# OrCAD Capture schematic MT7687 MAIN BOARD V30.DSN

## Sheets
1 4_LED: size C; title: MT76x7 Main Board; rev: 3.0; company: MediaTek Inc.; note: 4_LED
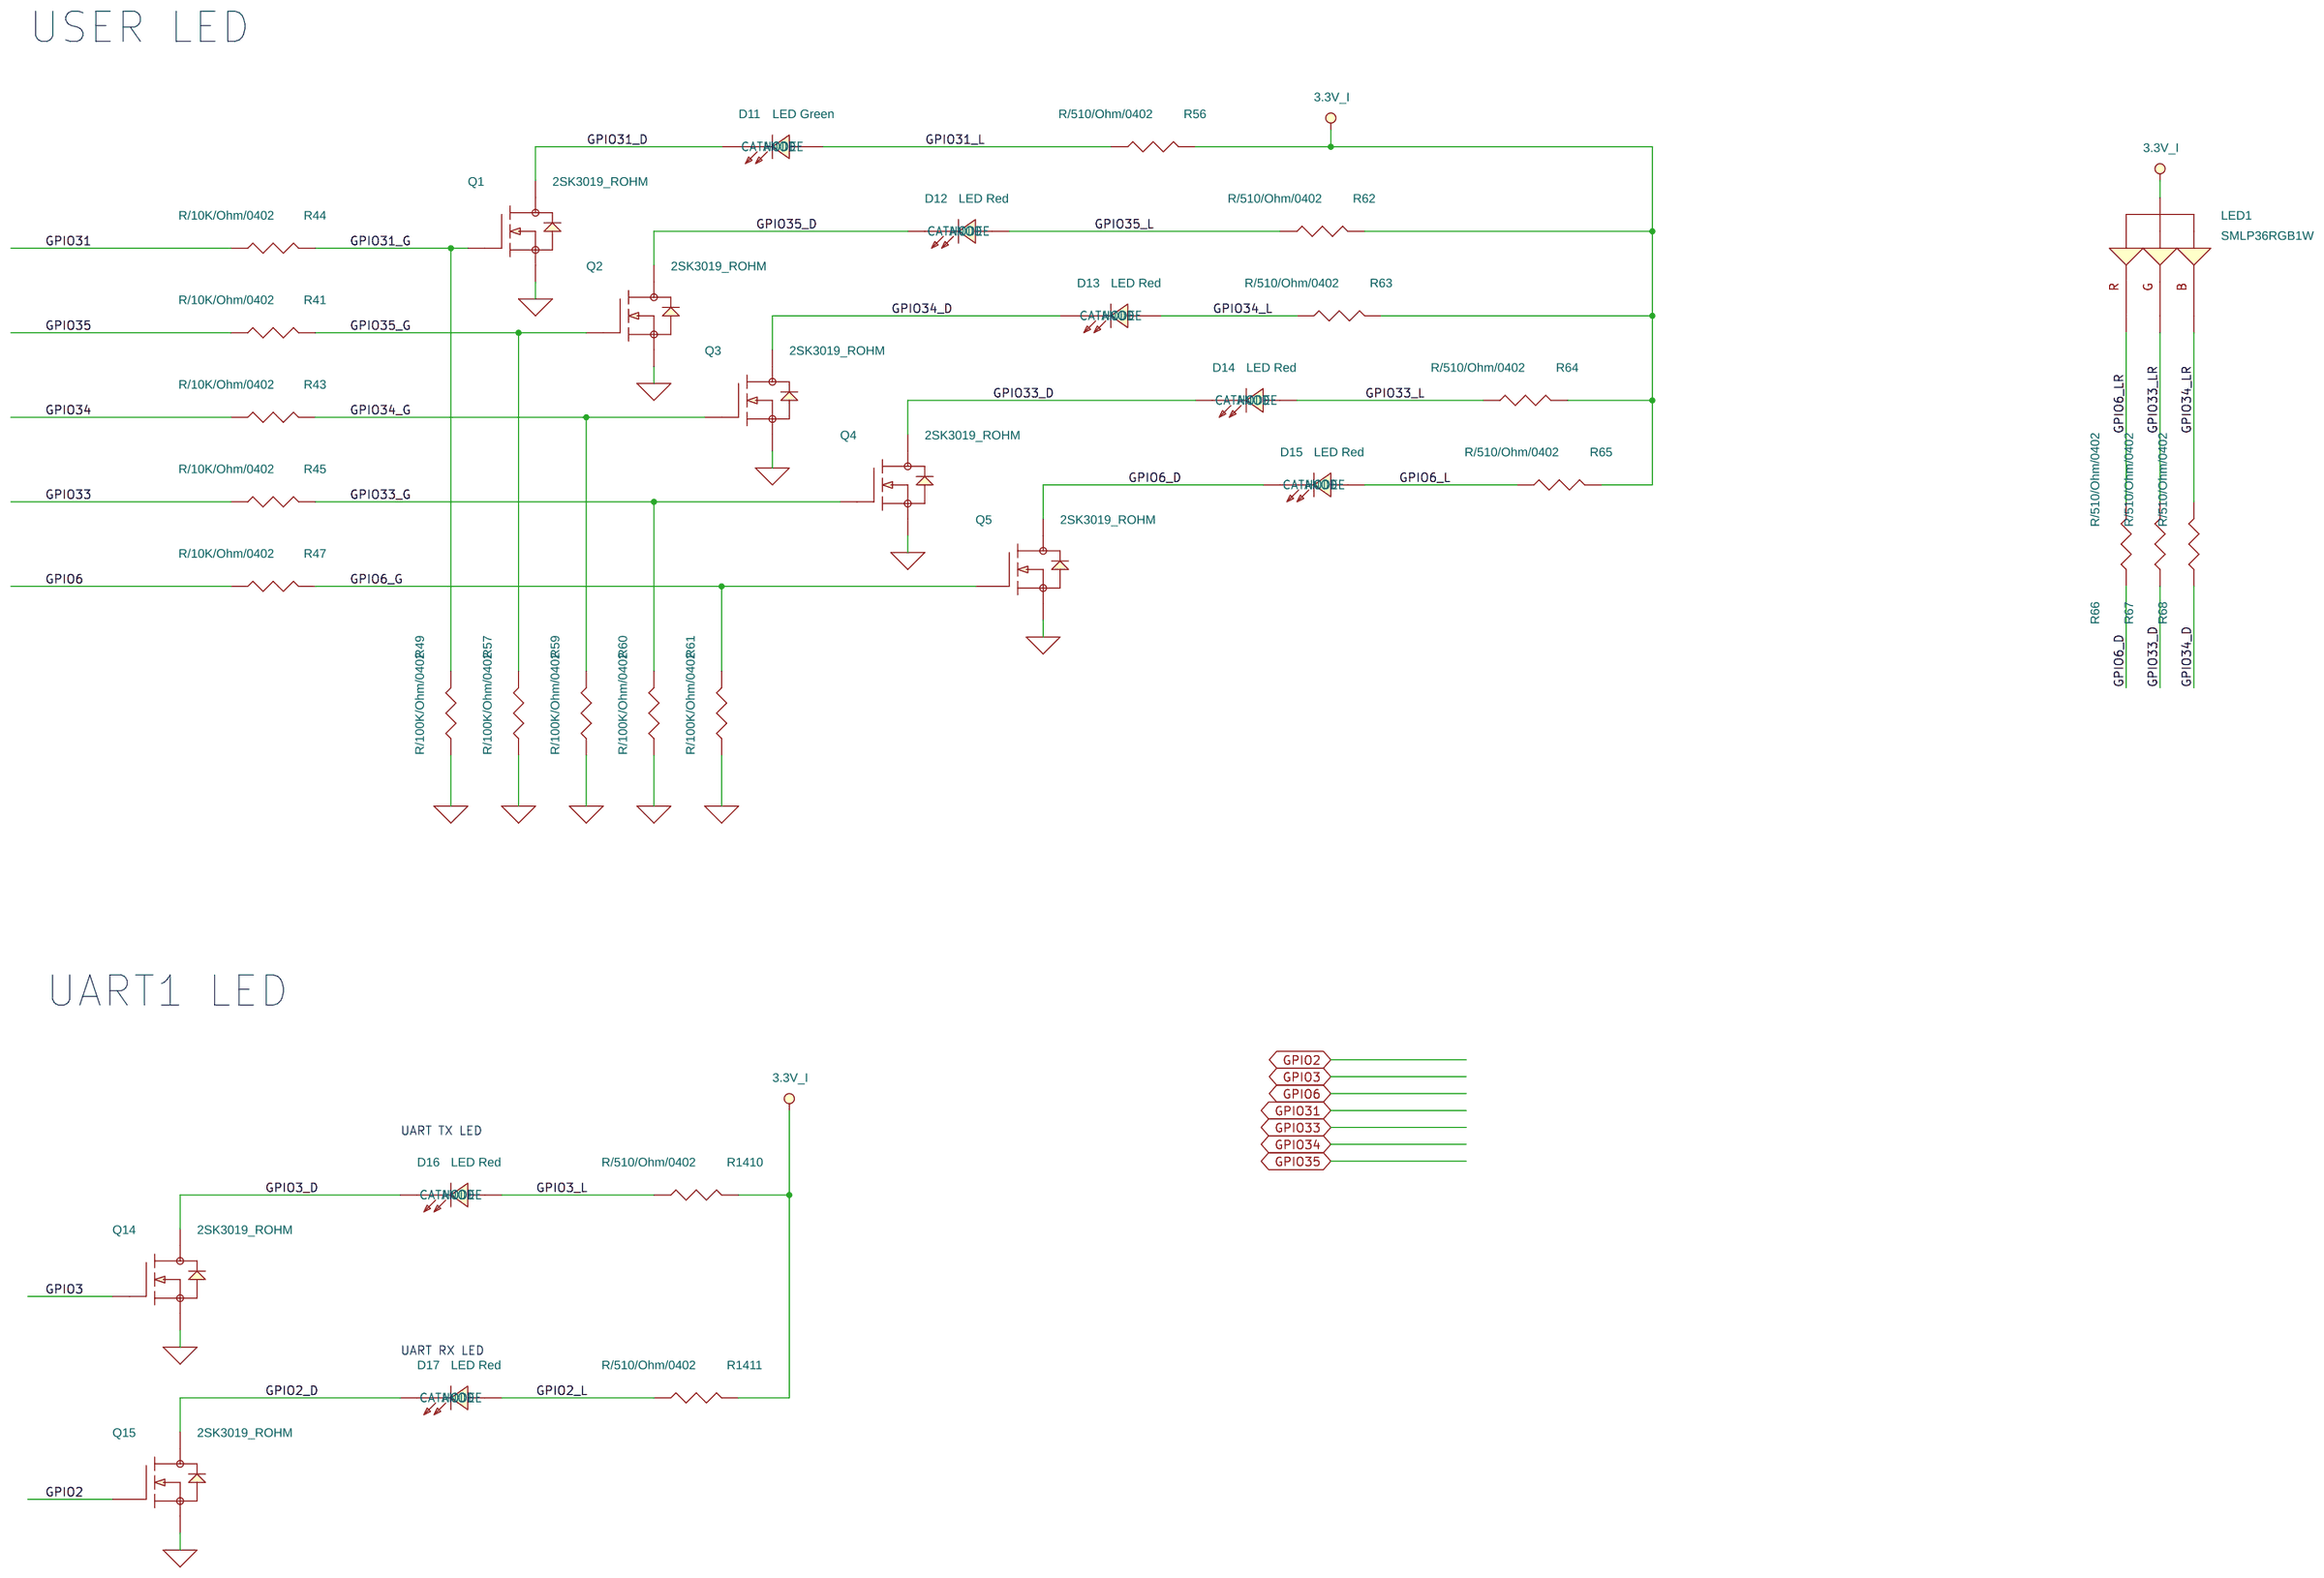
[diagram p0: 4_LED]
2 3_USB: size C; note: 3_USB
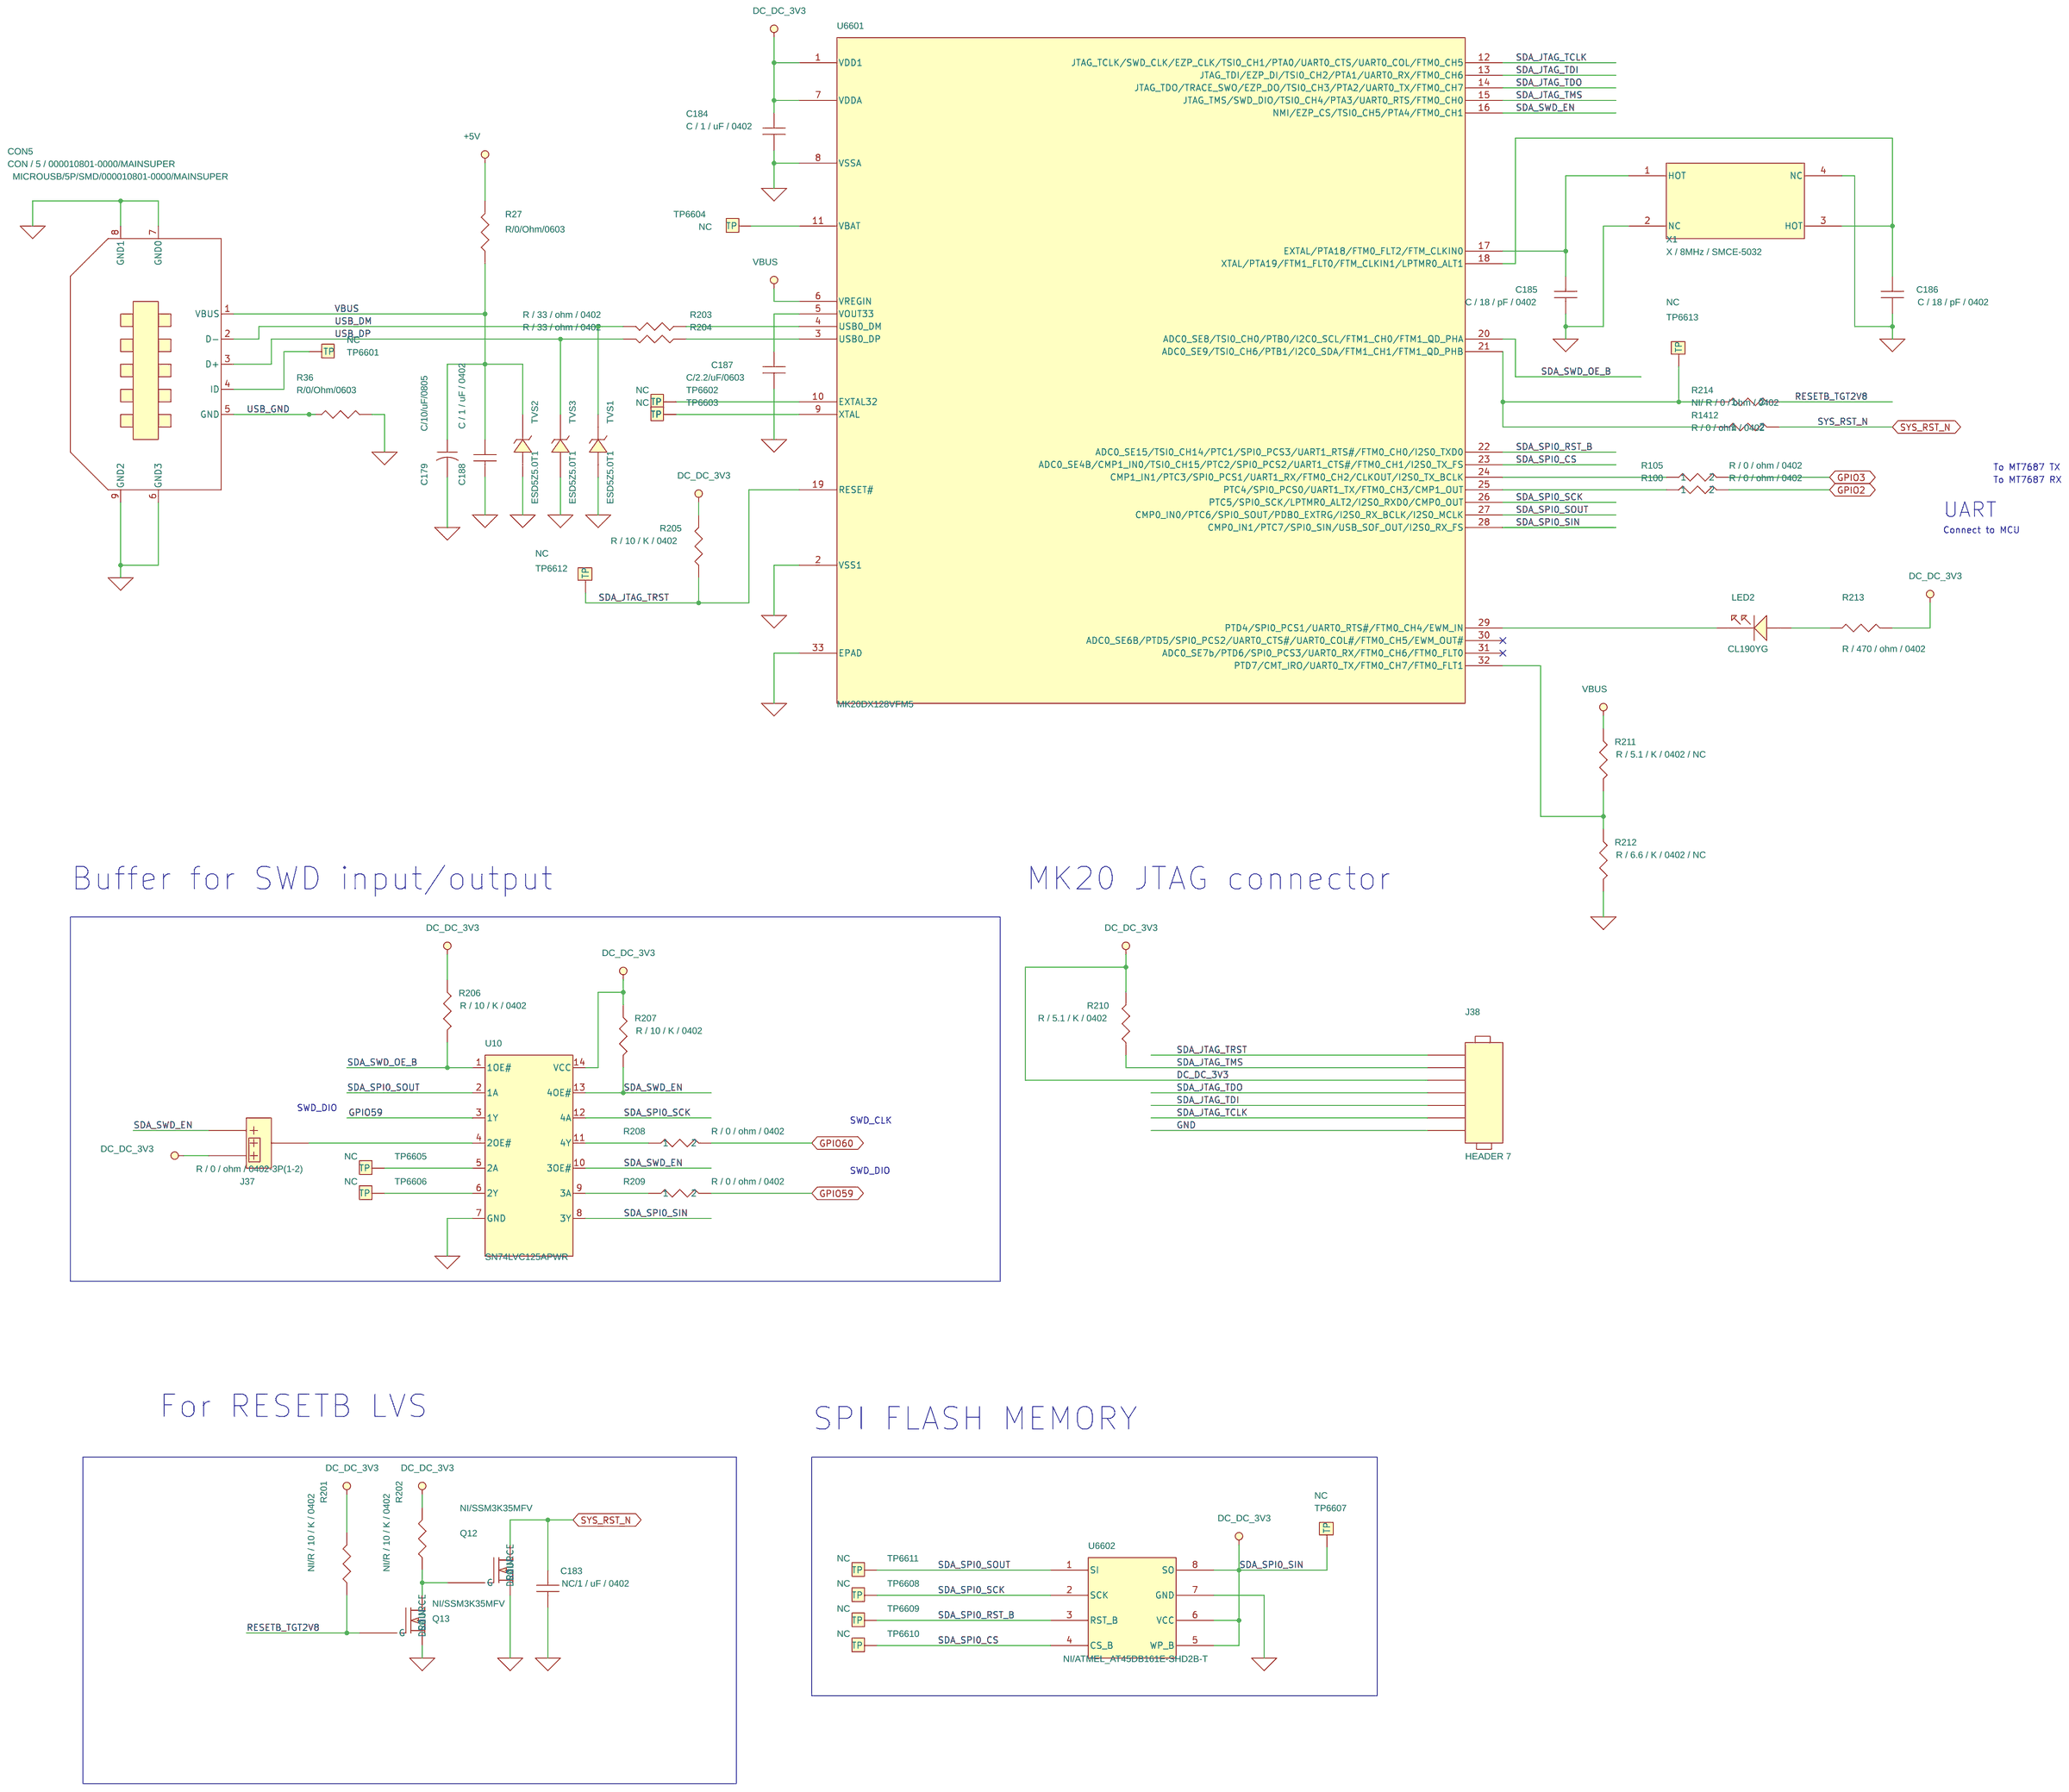
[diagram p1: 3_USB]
3 1_Power Tree: size C; note: 1-Power Tree
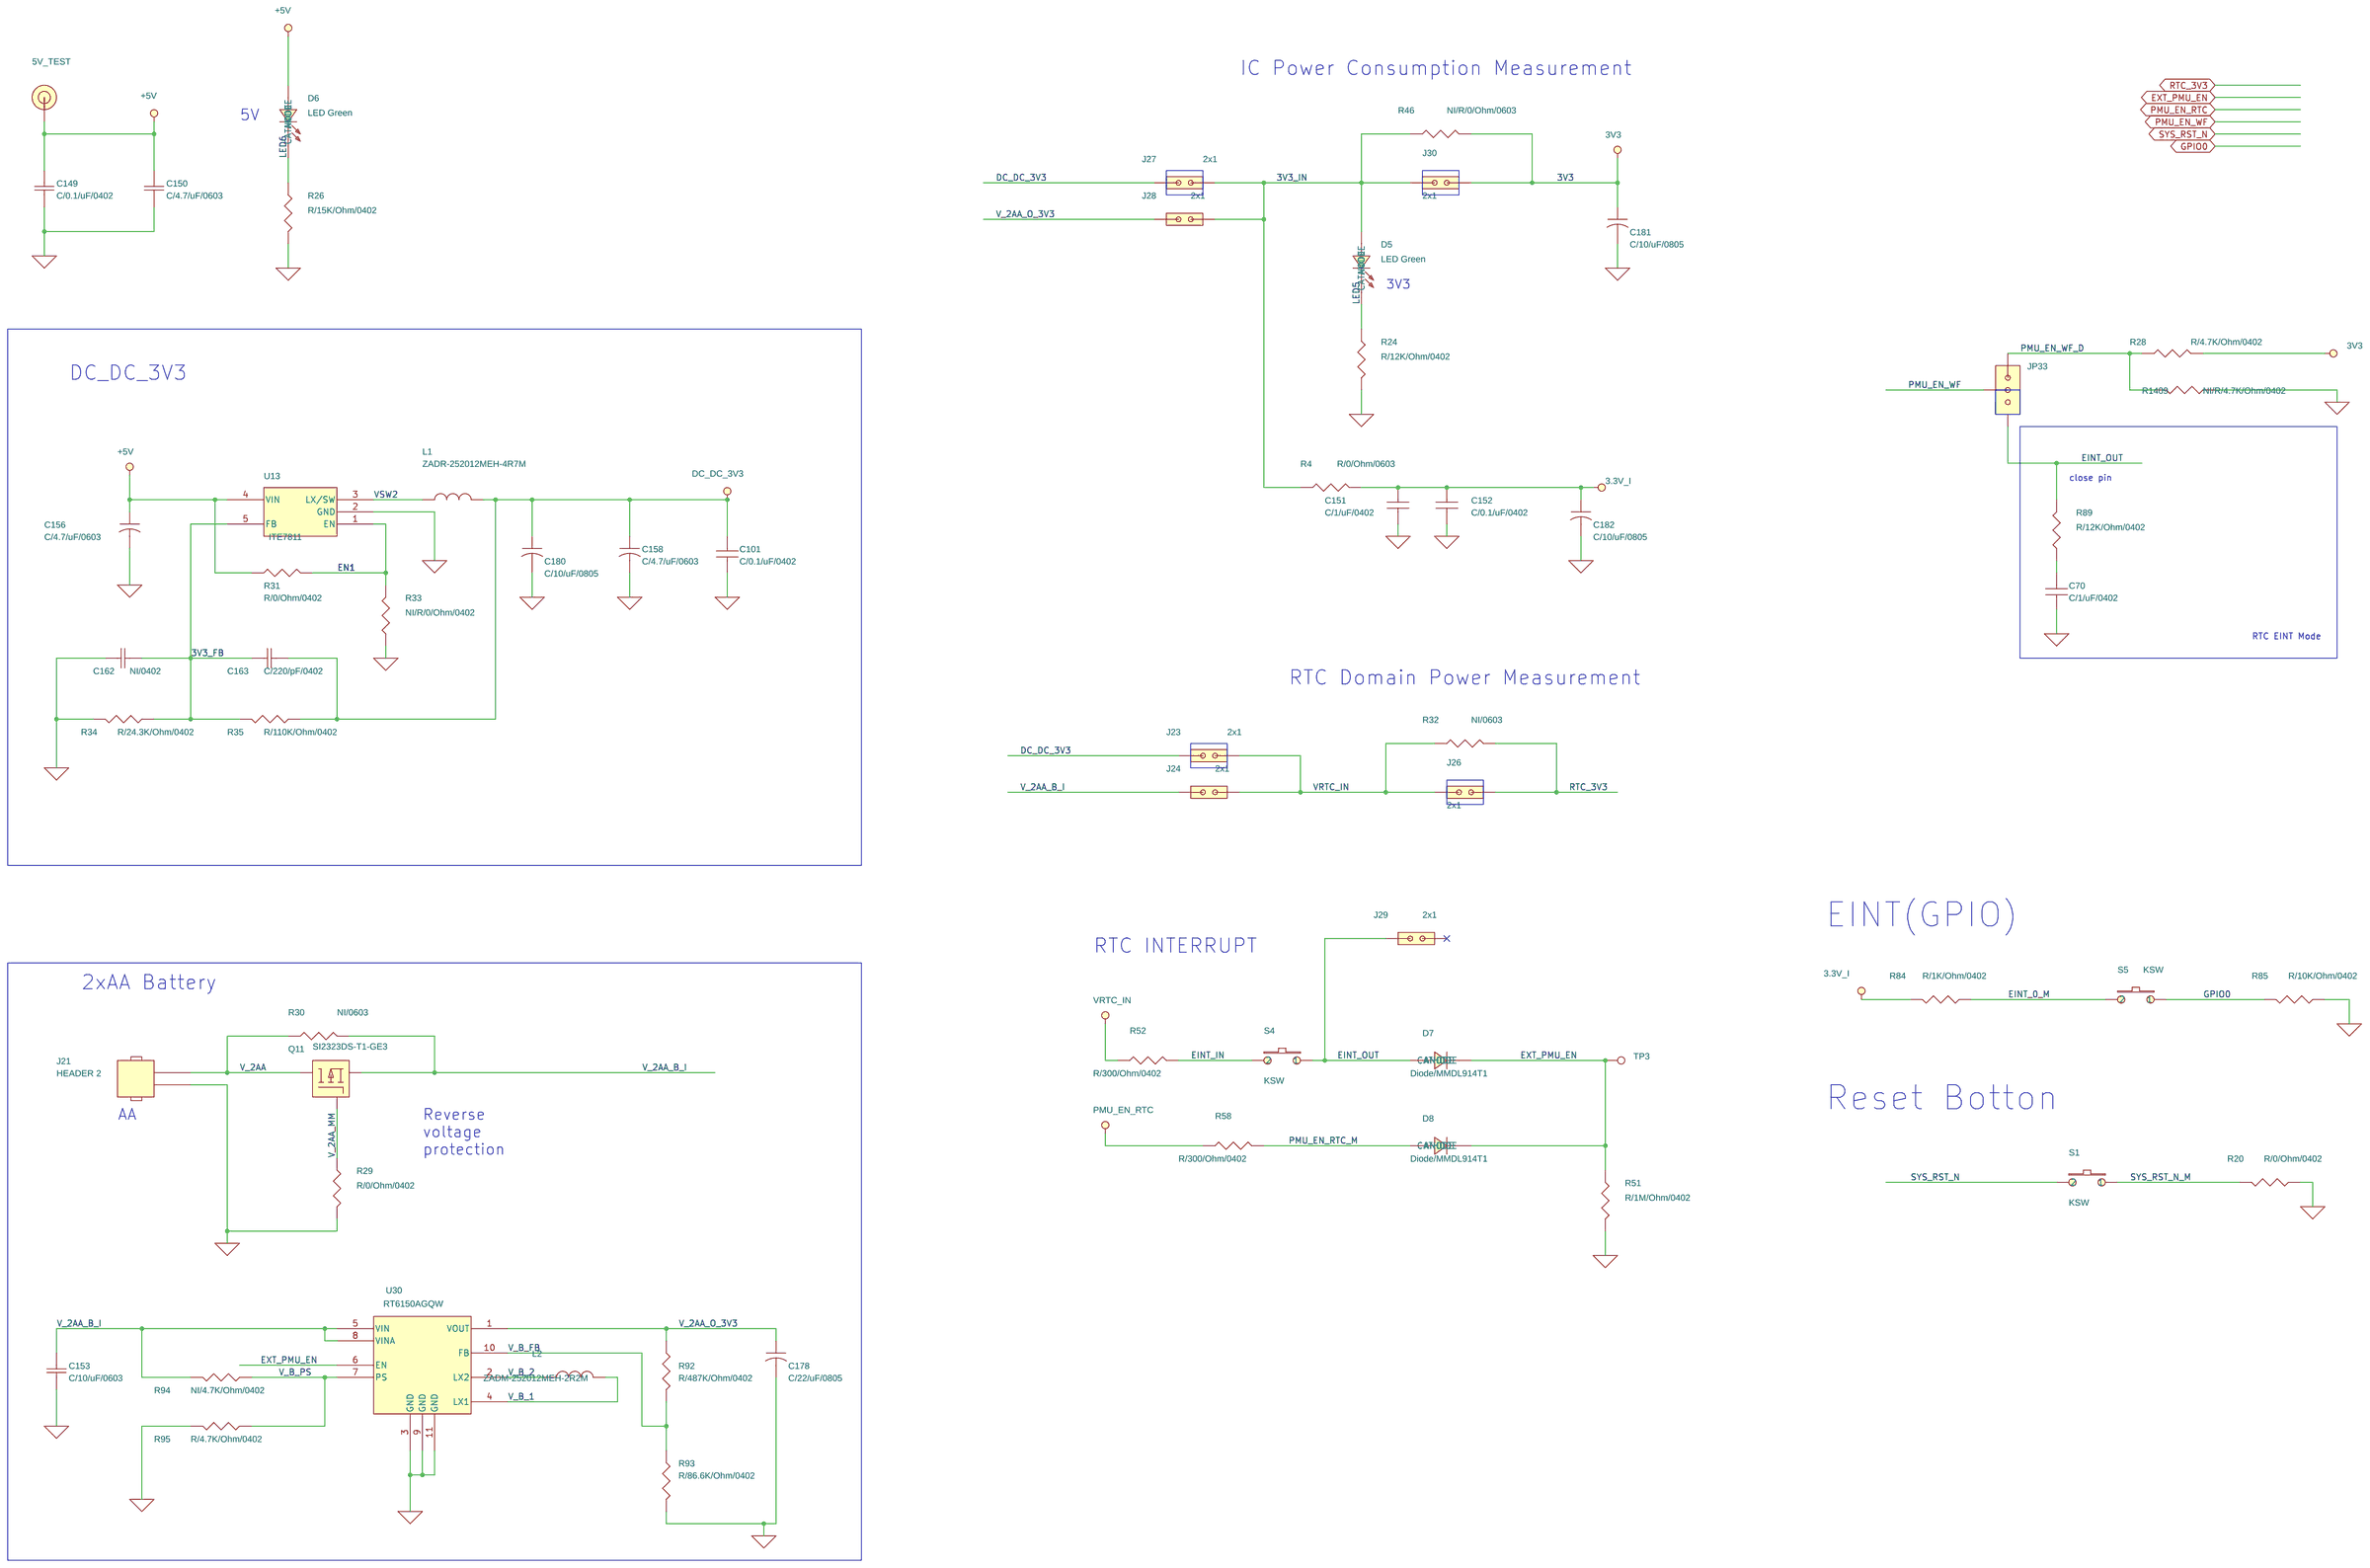
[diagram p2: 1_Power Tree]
4 2_Test Interface: size C; note: 2_Test Interface
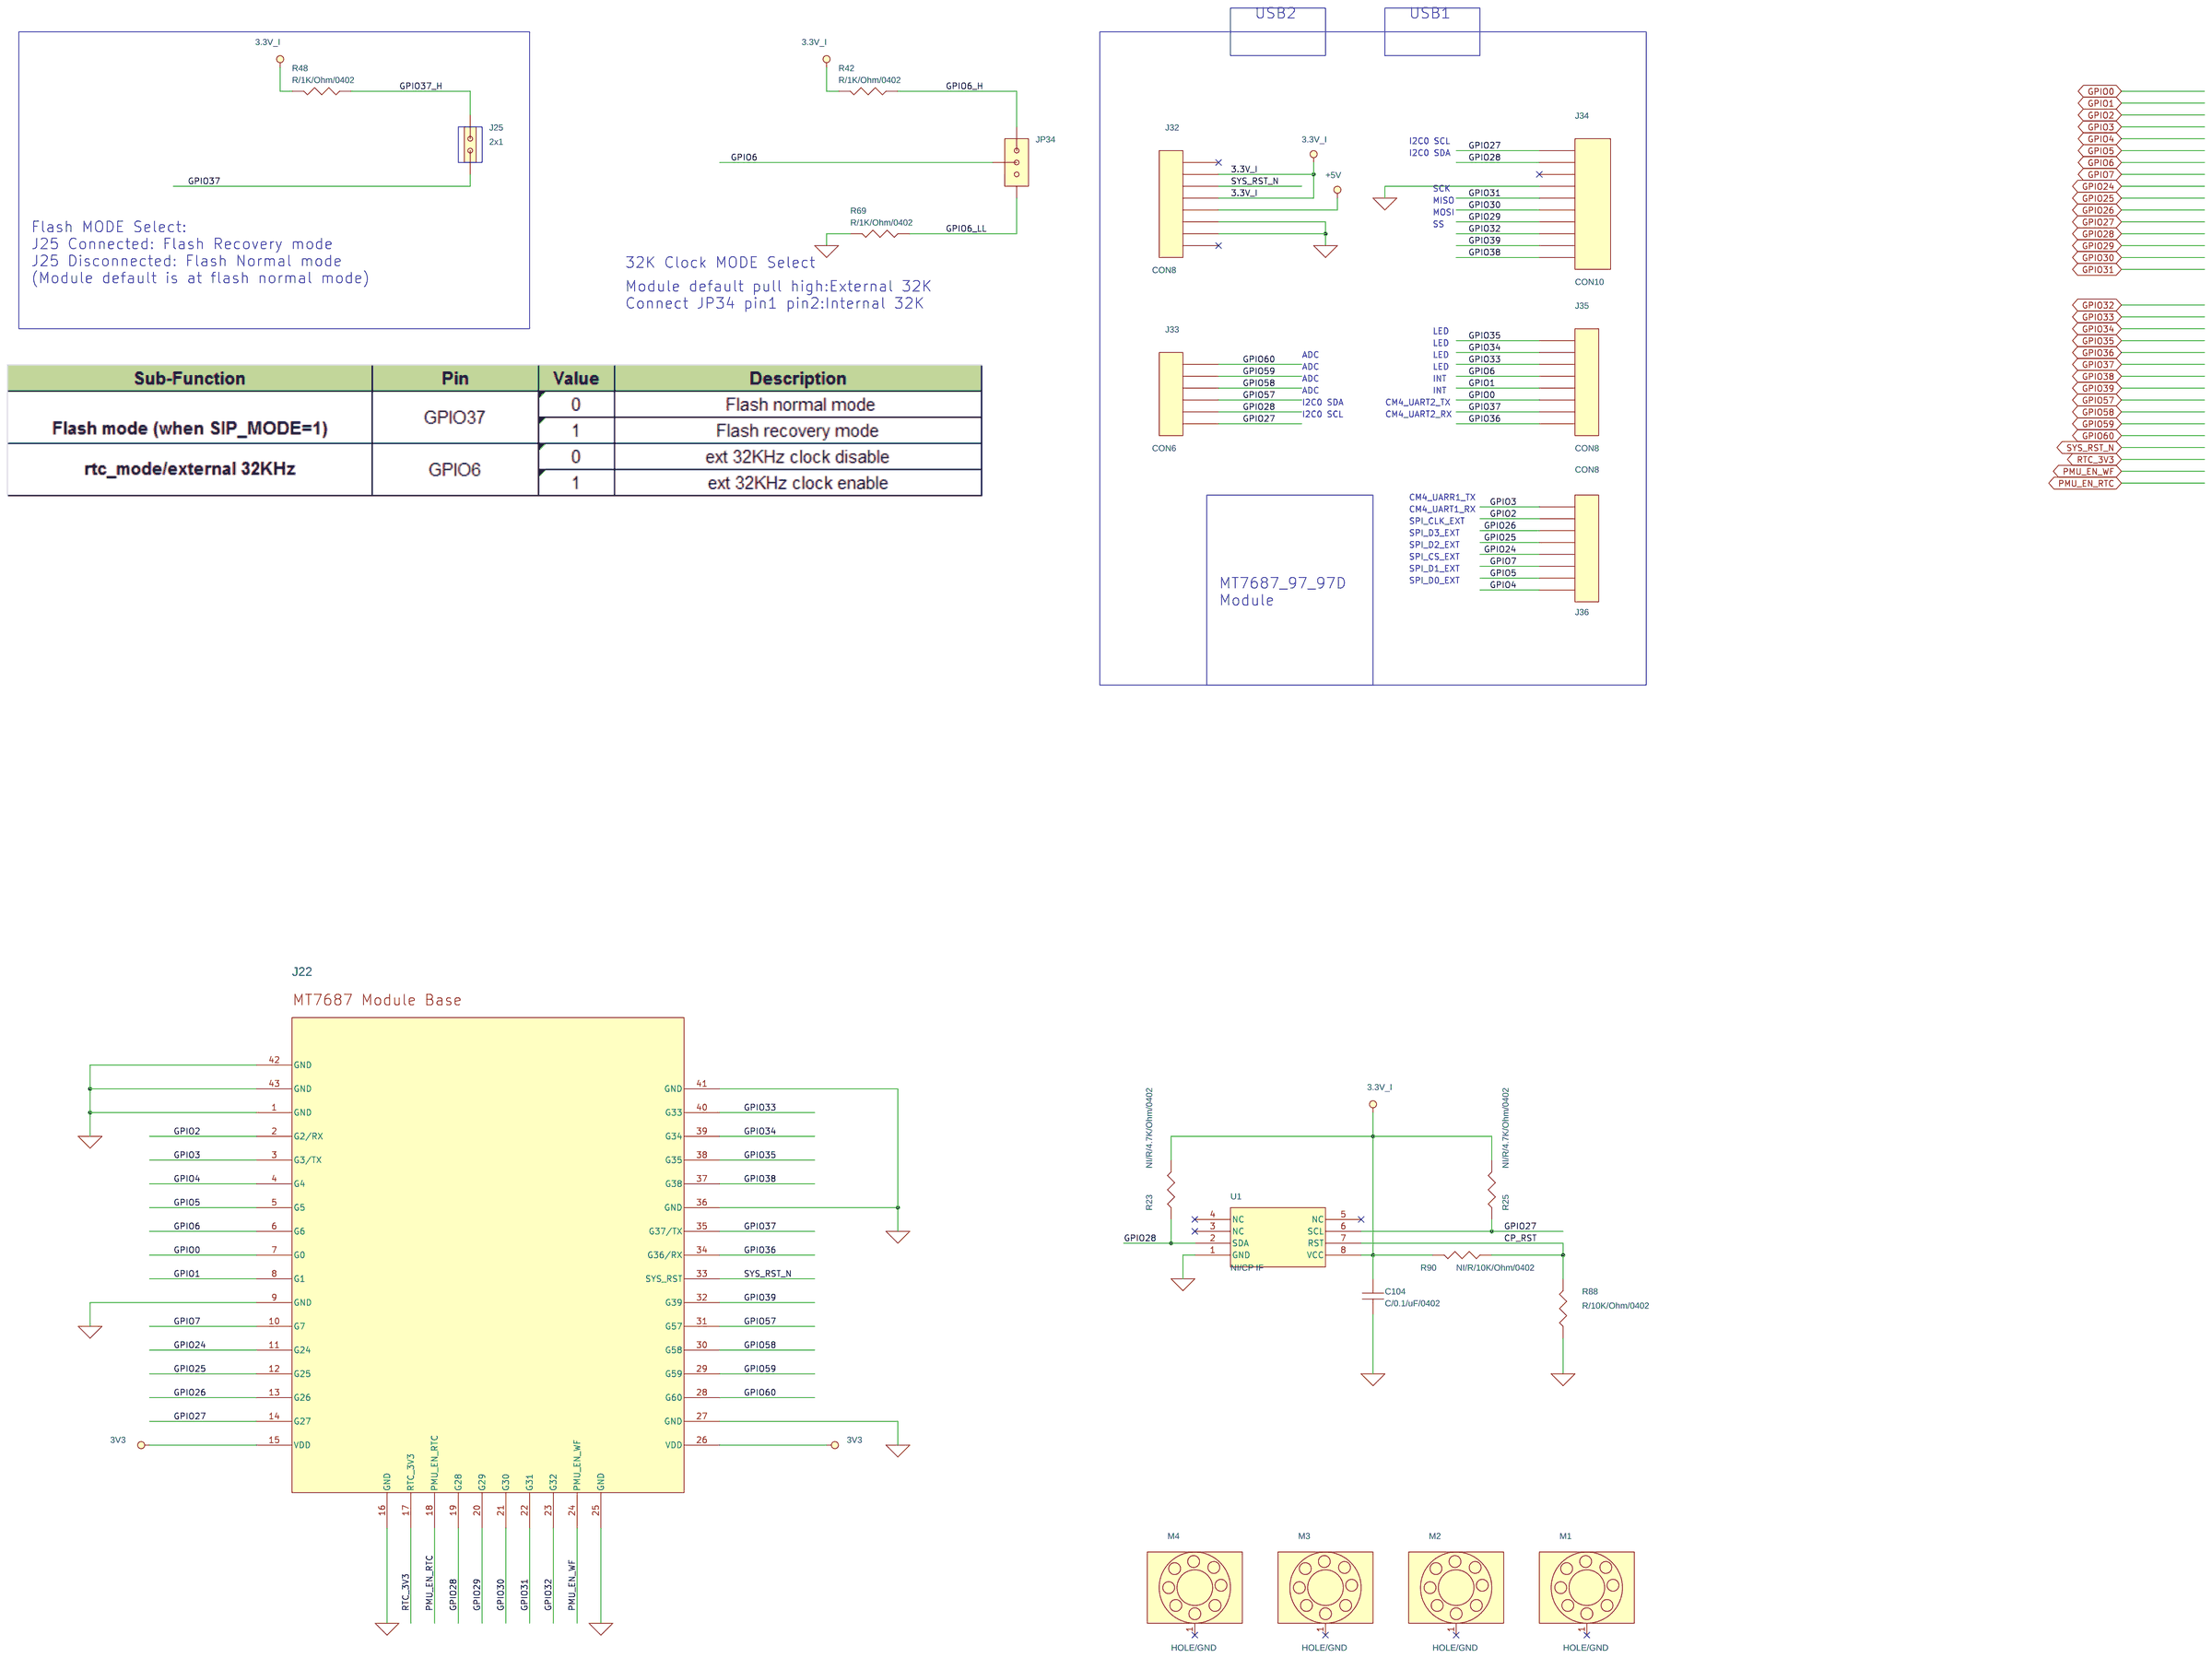
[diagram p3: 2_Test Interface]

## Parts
sheet 1_Power Tree
5V_TEST  TP-ICT  [HOLE/PTH/R1D0.6]
C70  C/1/uF/0402  [C0402]
C101  C/0.1/uF/0402  [C0402]
C149  C/0.1/uF/0402  [C0402]
C150  C/4.7/uF/0603  [C0603]
C151  C/1/uF/0402  [C0402]
C152  C/0.1/uF/0402  [C0402]
C153  C/10/uF/0603  [C0603]
C156  C/4.7/uF/0603  [C0603]
C158  C/4.7/uF/0603  [C0603]
C162  NI/0402  [C0402]
C163  C/220/pF/0402  [C0402]
C178  C/22/uF/0805  [C0805]
C180  C/10/uF/0805  [C0805]
C181  C/10/uF/0805  [C0805]
C182  C/10/uF/0805  [C0805]
D5  LED Green  [LED/SMD/0603]
D6  LED Green  [LED/SMD/0603]
D7  Diode/MMDL914T1  [SOD-323/SMD/MMDL914T1]
D8  Diode/MMDL914T1  [SOD-323/SMD/MMDL914T1]
J21  HEADER 2  [DIP2/P2.54]
J23  2x1  [JP2/DIP/P2.54]
J24  2x1  [JP2/DIP/P2.54]
J26  2x1  [JP2/DIP/P2.54]
J27  2x1  [JP2/DIP/P2.54]
J28  2x1  [JP2/DIP/P2.54]
J29  2x1  [JP2/DIP/P2.54]
J30  2x1  [JP2/DIP/P2.54]
JP33  3x1  [JP3/DIP/P2.54]
L1  ZADR-252012MEH-4R7M  [L/IND/SMD/VLS252010T]
L2  ZADM-252012MEH-2R2M  [L/IND/SMD/VLS252012E]
Q11  SI2323DS-T1-GE3  [SOT23/3P/SMD/SI2323DS]
R4  R/0/Ohm/0603  [R0603]
R20  R/0/Ohm/0402  [R0402]
R24  R/12K/Ohm/0402  [R0402]
R26  R/15K/Ohm/0402  [R0402]
R28  R/4.7K/Ohm/0402  [R0402]
R29  R/0/Ohm/0402  [R0402]
R30  NI/0603  [R0603]
R31  R/0/Ohm/0402  [R0402]
R32  NI/0603  [R0603]
R33  NI/R/0/Ohm/0402  [R0402]
R34  R/24.3K/Ohm/0402  [R0402]
R35  R/110K/Ohm/0402  [R0402]
R46  NI/R/0/Ohm/0603  [R0603]
R51  R/1M/Ohm/0402  [R0402]
R52  R/300/Ohm/0402  [R0402]
R58  R/300/Ohm/0402  [R0402]
R84  R/1K/Ohm/0402  [R0402]
R85  R/10K/Ohm/0402  [R0402]
R89  R/12K/Ohm/0402  [R0402]
R92  R/487K/Ohm/0402  [R0402]
R93  R/86.6K/Ohm/0402  [R0402]
R94  NI/4.7K/Ohm/0402  [R0402]
R95  R/4.7K/Ohm/0402  [R0402]
R1409  NI/R/4.7K/Ohm/0402  [R0402]
S1  KSW  [SW4P/DIP/WCP]
S4  KSW  [SW4P/DIP/WCP]
S5  KSW  [SW4P/DIP/WCP]
TP3  TP-SMD  [TP-SMD]
U13  ITE7811  [TSOT-25/SMD/IT7811TS]
U30  RT6150AGQW  [WDFN10/SMD/P0.5/RT6150]
sheet 2_Test Interface
C104  C/0.1/uF/0402  [C0402]
J22  MT7687 Module  [MODULE/43P/SMD/SB-MT7687-1]
J25  2x1  [JP2/DIP/P2.54]
J32  CON8  [DIP8/P2.54]
J33  CON6  [DIP6/P2.54]
J34  CON10  [DIP10/P2.54]
J35  CON8  [DIP8/P2.54]
J36  CON8  [DIP8/P2.54]
JP34  3x1  [JP3/DIP/P2.54]
M1  HOLE/GND  [HOLE/NPTH/D3]
M2  HOLE/GND  [HOLE/NPTH/D3]
M3  HOLE/GND  [HOLE/NPTH/D3]
M4  HOLE/GND  [HOLE/NPTH/D3]
R23  NI/R/4.7K/Ohm/0402  [R0402/FCS]
R25  NI/R/4.7K/Ohm/0402  [R0402/FCS]
R42  R/1K/Ohm/0402  [R0402]
R48  R/1K/Ohm/0402  [R0402]
R69  R/1K/Ohm/0402  [R0402]
R88  R/10K/Ohm/0402  [R0402]
R90  NI/R/10K/Ohm/0402  [R0402]
U1  NI/CP IF  [USON8/SMD/P0.5/CP]
sheet 3_USB
C179  C/10/uF/0805  [C0805]
C183  NC/1 / uF / 0402  [C0402]
C184  C / 1 / uF / 0402  [C0402]
C185  C / 18 / pF / 0402  [C0402]
C186  C / 18 / pF / 0402  [C0402]
C187  C/2.2/uF/0603  [C0603]
C188  C / 1 / uF / 0402  [C0402]
CON5  CON / 5 / 000010801-0000/MAINSUPER  [MICROUSB/5P/SMD/000010801-0000/MAINSUPER]
J37  R / 0 / ohm / 0402-3P(1-2)  [R0402/(1-2)]
J38  HEADER 7  [DIP7/P2.54]
LED2  CL190YG  [LED190]
Q12  NI/SSM3K35MFV  [2-1L1B/SMD/SSM3K35MFV]
Q13  NI/SSM3K35MFV  [2-1L1B/SMD/SSM3K35MFV]
R27  R/0/Ohm/0603  [R0603]
R36  R/0/Ohm/0603  [R0603]
R100  R / 0 / ohm / 0402  [R0402]
R105  R / 0 / ohm / 0402  [R0402]
R201  NI/R / 10 / K / 0402  [R0402]
R202  NI/R / 10 / K / 0402  [R0402]
R203  R / 33 / ohm / 0402  [R0402]
R204  R / 33 / ohm / 0402  [R0402]
R205  R / 10 / K / 0402  [R0402]
R206  R / 10 / K / 0402  [R0402]
R207  R / 10 / K / 0402  [R0402]
R208  R / 0 / ohm / 0402  [R0402]
R209  R / 0 / ohm / 0402  [R0402]
R210  R / 5.1 / K / 0402  [R0402]
R211  R / 5.1 / K / 0402 / NC  [R0402]
R212  R / 6.6 / K / 0402 / NC  [R0402]
R213  R / 470 / ohm / 0402  [R0402]
R214  NI/ R / 0 / ohm / 0402  [R0402]
R1412  R / 0 / ohm / 0402  [R0402]
TP6601  NC  [TP30MIL]
TP6602  NC  [TP30MIL]
TP6603  NC  [TP30MIL]
TP6604  NC  [TP30MIL]
TP6605  NC  [TP40MIL]
TP6606  NC  [TP40MIL]
TP6607  NC  [TP30MIL]
TP6608  NC  [TP30MIL]
TP6609  NC  [TP30MIL]
TP6610  NC  [TP30MIL]
TP6611  NC  [TP30MIL]
TP6612  NC  [TP30MIL]
TP6613  NC  [TP40MIL]
TVS1  ESD5Z5.0T1  [SOD523/ESD5Z2.5T1]
TVS2  ESD5Z5.0T1  [SOD523/ESD5Z2.5T1]
TVS3  ESD5Z5.0T1  [SOD523/ESD5Z2.5T1]
U10  SN74LVC125APWR  [TSSOP14/SMD/P0.65/DRV603]
U6601  MK20DX128VFM5  [QFN32/SMD/P0.5/98ARE10566D]
U6602  NI/ATMEL_AT45DB161E-SHD2B-T  [SOIC8/SMD]
X1  X / 8MHz / SMCE-5032  [CRYS/SMD/D5.0X3.2/5XAA08000152KF80Q3]
sheet 4_LED
D11  LED Green  [LED/SMD/0603]
D12  LED Red  [LED/SMD/0603]
D13  LED Red  [LED/SMD/0603]
D14  LED Red  [LED/SMD/0603]
D15  LED Red  [LED/SMD/0603]
D16  LED Red  [LED/SMD/0603]
D17  LED Red  [LED/SMD/0603]
LED1  SMLP36RGB1W  [LED/4P/SMD/19-237A]
Q1  2SK3019_ROHM  [SC-75]
Q2  2SK3019_ROHM  [SC-75]
Q3  2SK3019_ROHM  [SC-75]
Q4  2SK3019_ROHM  [SC-75]
Q5  2SK3019_ROHM  [SC-75]
Q14  2SK3019_ROHM  [SC-75]
Q15  2SK3019_ROHM  [SC-75]
R41  R/10K/Ohm/0402  [R0402]
R43  R/10K/Ohm/0402  [R0402]
R44  R/10K/Ohm/0402  [R0402]
R45  R/10K/Ohm/0402  [R0402]
R47  R/10K/Ohm/0402  [R0402]
R49  R/100K/Ohm/0402  [R0402]
R56  R/510/Ohm/0402  [R0402]
R57  R/100K/Ohm/0402  [R0402]
R59  R/100K/Ohm/0402  [R0402]
R60  R/100K/Ohm/0402  [R0402]
R61  R/100K/Ohm/0402  [R0402]
R62  R/510/Ohm/0402  [R0402]
R63  R/510/Ohm/0402  [R0402]
R64  R/510/Ohm/0402  [R0402]
R65  R/510/Ohm/0402  [R0402]
R66  R/510/Ohm/0402  [R0402]
R67  R/510/Ohm/0402  [R0402]
R68  R/510/Ohm/0402  [R0402]
R1410  R/510/Ohm/0402  [R0402]
R1411  R/510/Ohm/0402  [R0402]

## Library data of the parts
5V_TEST = TP-ICT_1
C70 = C_0402
C101 C104 C151 C152 = CAPACITOR_NON-POL: PART_NUMBER: C21-0402M104Y1EWLS; PART_TYPE: C21
C149 C150 C153 = CAP_0402
C156 = CAP_0603
C158 = CAP_0805_0603
C162 C163 = CAP_0402: 1st Part Field: 0402
C178-C182 = CAP_0805
D5 D6 D11-D17 = LED_0603_0402
D7 D8 = Diode-4023_0
J21 = HEADER_2
J23-J30 = JUMPER_2x1_DIP2.54
JP33 JP34 = JUMPER_3x1_DIP2_0.54
L1 L2 = L_2.5*2.0
Q11 = MOSFET_I_EP_GSD: MOSFET P-CH 20V 3.7A SOT23-3; Distributor_Part_Number: SI2323DS-T1-GE3CT-ND; Mfr_Name: Vishay; TI_Part_No: TI-MOSFET-SI2323DS-T1-GE3
R4 = R_510_ohm_0402
R20 R28 R89 = RESISTOR: PART_NUMBER: R31-0201J0R00FWLS0; PART_TYPE: R31
R24 R26 R27 R29 R30 R32 R36 R41 R43-R47 R49 R56 R57 R59-R68 R92 R93 R1410 R1411 = RES_0603_0
R31 R33 = RES_0402_5
R34 = RES_0402_2
R35 R51 R52 R58 = RES_0402_3
R84 R85 R88 R90 R1409 = RES_0402_1
R42 R48 R69 R94 R95 = R_0402
S1 = SW_PUSHBUTTON
S4 = SW_PUSHBUTTON_1
S5 = SW_PUSHBUTTON_2
TP3 = TP-SMD
U13 = REG_CAT7101
U30 = REG_CAT7117_4
J22 = S500_2
J32 J35 J36 = CON8
J33 = CON6
J34 = CON10
M1-M4 = HOLE_3_0.5mm
R23 R25 = RES_0402
U1 = CP_IF
C183 C184 C188 = C_1000_nF_0402
C185 C186 = C_18_pF_0402
C187 = C_10_uF_0603_X5R
CON5 = Mini_10pin_0
J37 = CON3_0
J38 = HEADER_3_3
LED2 = LED_1
Q12 Q13 = MOSFET_N_2
R100 = Resistor_5_3: R 0 J 1/16W 0402; Vendor: CYNTEC
R105 = Resistor_5: R 0 J 1/16W 0402; Vendor: CYNTEC
R201 R202 R205-R207 R210-R212 = R_10_K_0402
R203 R204 = R_0_ohm_0402
R208 = Resistor_5_4: R 0 J 1/16W 0402; Vendor: CYNTEC
R209 = Resistor_5_1: R 0 J 1/16W 0402; Vendor: CYNTEC
R213 = RESISTOR
R214 = Resistor_5_5: R 0 J 1/16W 0402; Vendor: CYNTEC
R1412 = Resistor_5_2: R 0 J 1/16W 0402; Vendor: CYNTEC
TP6601-TP6613 = T_POINT_F_2
TVS1-TVS3 = TVS_SOD523
U10 = CON_10_AXT510124_0: ebom: USB
U6601 = 74ALVC164245_2: Vendor: TI
U6602 = X_26_MHz_TZ2300A_0
X1 = TCVCXO_1: TCVCXO 26MHz; Customer PN: 70TZ1879A00F; Manufacturer Part Number: TZ1879A; Part Type: Crystal\OSC; Vendor: Taisaw
LED1 = DIODE_10: Diode RB551V-30; Layer: Top; PN: RB520S-30; Vendor: Rohm
Q1-Q5 Q14 Q15 = MPF6659_0: Layer: Top

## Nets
3.3V_I: C104.1 C151.1 C152.1 C182.1 J32.2 J32.4 LED1.4 R4.2 R23.1 R25.1 R42.1 R48.1 R56.1 R62.1 R63.1 R64.1 R65.1 R84.1 R90.1 R1410.1 R1411.1 U1.8(VCC)
3V3: C181.1 J22.15(VDD) J22.26(VDD) J30.2 R28.2 R46.2
3V3_FB: C162.2 C163.1 R34.1 R35.2 U13.5(FB)
3V3_IN: D5.1(ANODE) J27.2 J28.2 J30.1 R4.1 R46.1
+5V: 5V_TEST.1 C149.1 C150.1 C156.1 D6.1(ANODE) J32.5 R27.2 R31.1 U13.4(VIN)
GND: C70.1 C101.2 C104.2 C149.2 C150.2 C151.2 C152.2 C153.2 C156.2 C158.2 C162.1 C178.2 C179.2 C180.2 C181.2 C182.2 C183.2 C184.2 C185.2 C186.2 C187.2 C188.2 CON5.6(GND3) CON5.7(GND0) CON5.8(GND1) CON5.9(GND2) J21.2 J22.1(GND) J22.9(GND) J22.16(GND) J22.25(GND) J22.27(GND) J22.36(GND) J22.41(GND) J22.42(GND) J22.43(GND) J32.6 J32.7 J34.4 J38.1 Q1.1(S) Q2.1(S) Q3.1(S) Q4.1(S) Q5.1(S) Q12.2(SOURCE) Q13.2(SOURCE) Q14.1(S) Q15.1(S) R20.1 R24.2 R26.2 R29.2 R33.1 R34.2 R36.2 R49.2 R51.2 R57.2 R59.2 R60.2 R61.2 R69.1 R85.2 R88.2 R93.2 R95.1 R212.2 R1409.2 TVS1.A TVS2.A TVS3.A U1.1(GND) U10.7(GND) U13.2(GND) U30.3(GND) U30.9(GND) U30.11(GND) U6601.2(VSS1) U6601.8(VSSA) U6601.33(EPAD) U6602.7(GND) X1.2(NC) X1.4(NC)
VBUS: C179.1 C188.1 CON5.1(VBUS) R27.1 R211.1 TVS2.K U6601.6(VREGIN)
CP_RST: R88.1 R90.2 U1.7(RST)
DC_DC_3V3: C101.1 C158.1 C163.2 C180.1 C184.1 J23.1 J27.1 J37.1 J38.5 L1.2 R35.1 R201.1 R202.1 R205.1 R206.1 R207.1 R210.1 R213.2 U10.14(VCC) U6601.1(VDD1) U6601.7(VDDA) U6602.5(WP_B) U6602.6(VCC)
EINT_0_M: R84.2 S5.2
EINT_IN: R52.2 S4.2
EINT_OUT: D7.2(ANODE) J29.1 JP33.1 R89.2 S4.1
EN1: R31.2 R33.2 U13.1(EN)
EXT_PMU_EN: D7.1(CATHODE) D8.1(CATHODE) R51.1 TP3.1 U30.6(EN)
GPIO0: J22.7(G0) J35.6 R85.1 S5.1
GPIO1: J22.8(G1) J35.5
GPIO2: J22.2(G2/RX) J36.7 Q15.2(G) R100.2
GPIO2_D: D17.2(CATHODE) Q15.3(D)
GPIO2_L: D17.1(ANODE) R1411.2
GPIO3: J22.3(G3/TX) J36.8 Q14.2(G) R105.2
GPIO3_D: D16.2(CATHODE) Q14.3(D)
GPIO3_L: D16.1(ANODE) R1410.2
GPIO4: J22.4(G4) J36.1
GPIO5: J22.5(G5) J36.2
GPIO6: J22.6(G6) J35.4 JP34.2 R47.2
GPIO6_D: D15.2(CATHODE) Q5.3(D) R66.2
GPIO6_G: Q5.2(G) R47.1 R61.1
GPIO6_H: JP34.3 R42.2
GPIO6_L: D15.1(ANODE) R65.2
GPIO6_LL: JP34.1 R69.2
GPIO6_LR: LED1.1 R66.1
GPIO7: J22.10(G7) J36.3
GPIO24: J22.11(G24) J36.4
GPIO25: J22.12(G25) J36.5
GPIO26: J22.13(G26) J36.6
GPIO27: J22.14(G27) J33.6 J34.1 R25.2 U1.6(SCL)
GPIO28: J22.19(G28) J33.5 J34.2 R23.2 U1.2(SDA)
GPIO29: J22.20(G29) J34.7
GPIO30: J22.21(G30) J34.6
GPIO31: J22.22(G31) J34.5 R44.2
GPIO31_D: D11.2(CATHODE) Q1.3(D)
GPIO31_G: Q1.2(G) R44.1 R49.1
GPIO31_L: D11.1(ANODE) R56.2
GPIO32: J22.23(G32) J34.8
GPIO33: J22.40(G33) J35.3 R45.2
GPIO33_D: D14.2(CATHODE) Q4.3(D) R67.2
GPIO33_G: Q4.2(G) R45.1 R60.1
GPIO33_L: D14.1(ANODE) R64.2
GPIO33_LR: LED1.2 R67.1
GPIO34: J22.39(G34) J35.2 R43.2
GPIO34_D: D13.2(CATHODE) Q3.3(D) R68.2
GPIO34_G: Q3.2(G) R43.1 R59.1
GPIO34_L: D13.1(ANODE) R63.2
GPIO34_LR: LED1.3 R68.1
GPIO35: J22.38(G35) J35.1 R41.2
GPIO35_D: D12.2(CATHODE) Q2.3(D)
GPIO35_G: Q2.2(G) R41.1 R57.1
GPIO35_L: D12.1(ANODE) R62.2
GPIO36: J22.34(G36/RX) J35.8
GPIO37: J22.35(G37/TX) J25.1 J35.7
GPIO37_H: J25.2 R48.2
GPIO38: J22.37(G38) J34.10
GPIO39: J22.32(G39) J34.9
GPIO57: J22.31(G57) J33.4
GPIO58: J22.30(G58) J33.3
GPIO59: J22.29(G59) J33.2 R209.2 U10.3(1Y)
GPIO60: J22.28(G60) J33.1 R208.2
LED5: D5.2(CATHODE) R24.1
LED6: D6.2(CATHODE) R26.1
PMU_EN_RTC: J22.18(PMU_EN_RTC) R58.1
PMU_EN_RTC_M: D8.2(ANODE) R58.2
PMU_EN_WF: J22.24(PMU_EN_WF) JP33.2
PMU_EN_WF_D: JP33.3 R28.1 R1409.1
RESETB_TGT2V8: Q13.1(G) R201.2 R214.2
RTC_3V3: J22.17(RTC_3V3) J26.2 R32.2
SDA_JTAG_TCLK: J38.2 U6601.12(JTAG_TCLK/SWD_CLK/EZP_CLK/TSI0_CH1/PTA0/UART0_CTS/UART0_COL/FTM0_CH5)
SDA_JTAG_TDI: J38.3 U6601.13(JTAG_TDI/EZP_DI/TSI0_CH2/PTA1/UART0_RX/FTM0_CH6)
SDA_JTAG_TDO: J38.4 U6601.14(JTAG_TDO/TRACE_SWO/EZP_DO/TSI0_CH3/PTA2/UART0_TX/FTM0_CH7)
SDA_JTAG_TMS: J38.6 R210.2 U6601.15(JTAG_TMS/SWD_DIO/TSI0_CH4/PTA3/UART0_RTS/FTM0_CH0)
SDA_JTAG_TRST: J38.7 R205.2 TP6612.1(TP) U6601.19(RESET#)
SDA_SPI0_CS: TP6610.1(TP) U6601.23(ADC0_SE4B/CMP1_IN0/TSI0_CH15/PTC2/SPI0_PCS2/UART1_CTS#/FTM0_CH1/I2S0_TX_FS) U6602.4(CS_B)
SDA_SPI0_RST_B: TP6609.1(TP) U6601.22(ADC0_SE15/TSI0_CH14/PTC1/SPI0_PCS3/UART1_RTS#/FTM0_CH0/I2S0_TXD0) U6602.3(RST_B)
SDA_SPI0_SCK: TP6608.1(TP) U10.12(4A) U6601.26(PTC5/SPI0_SCK/LPTMR0_ALT2/I2S0_RXD0/CMP0_OUT) U6602.2(SCK)
SDA_SPI0_SIN: TP6607.1(TP) U10.8(3Y) U6601.28(CMP0_IN1/PTC7/SPI0_SIN/USB_SOF_OUT/I2S0_RX_FS) U6602.8(SO)
SDA_SPI0_SOUT: TP6611.1(TP) U10.2(1A) U6601.27(CMP0_IN0/PTC6/SPI0_SOUT/PDB0_EXTRG/I2S0_RX_BCLK/I2S0_MCLK) U6602.1(SI)
SDA_SWD_EN: J37.3 R207.2 U10.10(3OE#) U10.13(4OE#) U6601.16(NMI/EZP_CS/TSI0_CH5/PTA4/FTM0_CH1)
SDA_SWD_OE_B: R206.2 U10.1(1OE#) U6601.20(ADC0_SE8/TSI0_CH0/PTB0/I2C0_SCL/FTM1_CH0/FTM1_QD_PHA)
SYS_RST_N: C183.1 J22.33(SYS_RST) J32.3 Q12.3(DRAIN) R1412.2 S1.2
SYS_RST_N_M: R20.2 S1.1
USB_DM: CON5.2(D-) R203.1 TVS1.K
USB_DP: CON5.3(D+) R204.1 TVS3.K
USB_GND: CON5.5(GND) R36.1
V_2AA: J21.1 Q11.3(D) R30.1
V_2AA_B_I: C153.1 J24.1 Q11.2(S) R30.2 R94.1 U30.5(VIN) U30.8(VINA)
V_2AA_MM: Q11.1(G) R29.1
V_2AA_O_3V3: C178.1 J28.1 R92.1 U30.1(VOUT)
V_B_1: L2.2 U30.4(LX1)
V_B_2: L2.1 U30.2(LX2)
V_B_FB: R92.2 R93.1 U30.10(FB)
V_B_PS: R94.2 R95.2 U30.7(PS)
VRTC_IN: J23.2 J24.2 J26.1 R32.1 R52.1
VSW2: L1.1 U13.3(LX/SW)
N19175655: CON5.4(ID) TP6601.1(TP)
N19176000: C185.1 U6601.17(EXTAL/PTA18/FTM0_FLT2/FTM_CLKIN0) X1.1(HOT)
N19176004: C186.1 U6601.18(XTAL/PTA19/FTM1_FLT0/FTM_CLKIN1/LPTMR0_ALT1) X1.3(HOT)
N19176010: R211.2 R212.1 U6601.32(PTD7/CMT_IRO/UART0_TX/FTM0_CH7/FTM0_FLT1)
N19176024: LED2.2 U6601.29(PTD4/SPI0_PCS1/UART0_RTS#/FTM0_CH4/EWM_IN)
N19176065: TP6604.1(TP) U6601.11(VBAT)
N19176071: TP6602.1(TP) U6601.10(EXTAL32)
N19176073: TP6603.1(TP) U6601.9(XTAL)
N19176075: C187.1 U6601.5(VOUT33)
N19176081: R203.2 U6601.4(USB0_DM)
N19176083: R204.2 U6601.3(USB0_DP)
N19176140: R214.1 R1412.1 TP6613.1(TP) U6601.21(ADC0_SE9/TSI0_CH6/PTB1/I2C0_SDA/FTM1_CH1/FTM1_QD_PHB)
N19176148: R100.1 U6601.25(PTC4/SPI0_PCS0/UART1_TX/FTM0_CH3/CMP1_OUT)
N19176150: R105.1 U6601.24(CMP1_IN1/PTC3/SPI0_PCS1/UART1_RX/FTM0_CH2/CLKOUT/I2S0_TX_BCLK)
N19183861: LED2.1 R213.1
N19224016: TP6605.1(TP) U10.5(2A)
N19224018: TP6606.1(TP) U10.6(2Y)
N19224201: R208.1 U10.11(4Y)
N19224206: R209.1 U10.9(3A)
N19224211: J37.2 U10.4(2OE#)
N19236054: C70.2 R89.1
N19237278: Q12.1(G) Q13.3(DRAIN) R202.2

Not connected (* = marked no-connect by the designer): J29 2*; J32 1* 8*; J34 3*; M1 1*; M2 1*; M3 1*; M4 1*; U1 3(NC)* 4(NC)* 5(NC)*; U6601 30(ADC0_SE6B/PTD5/SPI0_PCS2/UART0_CTS#/UART0_COL#/FTM0_CH5/EWM_OUT#)* 31(ADC0_SE7b/PTD6/SPI0_PCS3/UART0_RX/FTM0_CH6/FTM0_FLT0)*

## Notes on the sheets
sheet 1
- USER LED
- UART1 LED
- UART TX LED
- UART RX LED
sheet 2
- To MT7687 TX
- To MT7687 RX
- UART
- Connect to MCU
- Buffer for SWD input/output
- MK20 JTAG connector
- SWD_DIO
- SWD_CLK
- SWD_DIO
- For RESETB LVS
- SPI FLASH MEMORY
sheet 3
- IC Power Consumption Measurement
- 5V
- 3V3
- DC_DC_3V3
- close pin
- RTC EINT Mode
- RTC Domain Power Measurement
- EINT(GPIO)
- RTC INTERRUPT
- 2xAA Battery
- Reset Botton
- AA
- Reverse
  voltage
  protection
sheet 4
- USB2
- USB1
- I2C0 SCL
- I2C0 SDA
- SCK
- MISO
- MOSI
- Flash MODE Select:
  J25 Connected: Flash Recovery mode
  J25 Disconnected: Flash Normal mode
  (Module default is at flash normal mode)
- SS
- 32K Clock MODE Select
- Module default pull high:External 32K
  Connect JP34 pin1 pin2:Internal 32K
- LED
- LED
- ADC
- ADC
- LED
- LED
- ADC
- INT
- ADC
- INT
- I2C0 SDA
- CM4_UART2_TX
- I2C0 SCL
- CM4_UART2_RX
- CM4_UARR1_TX
- CM4_UART1_RX
- SPI_CLK_EXT
- SPI_D3_EXT
- SPI_D2_EXT
- SPI_CS_EXT
- SPI_D1_EXT
- MT7687_97_97D
  Module
- SPI_D0_EXT
